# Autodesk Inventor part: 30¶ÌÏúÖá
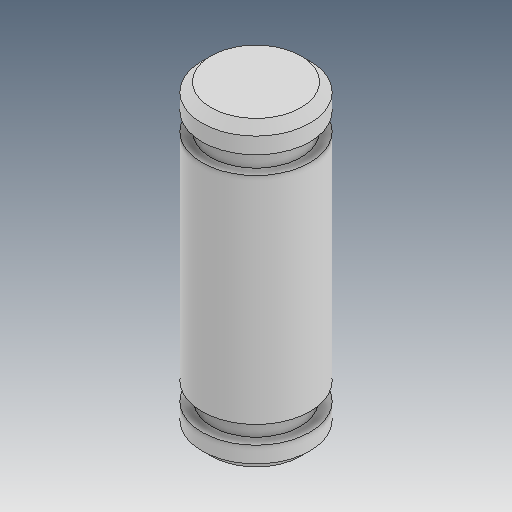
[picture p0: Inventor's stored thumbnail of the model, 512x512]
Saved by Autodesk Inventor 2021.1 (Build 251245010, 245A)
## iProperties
Created: 2019-04
Part Number: 30¶ÌÏúÖá
Material: Ogólny
Document SubType Name: Modeling
Designer: user
Density: 1 g/cm^3
Appearance: Domyślna
Author: user
Revision Number: ÈÎºÎ
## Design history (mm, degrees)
feature "ÊäÈë1"
node "Bryła1"
